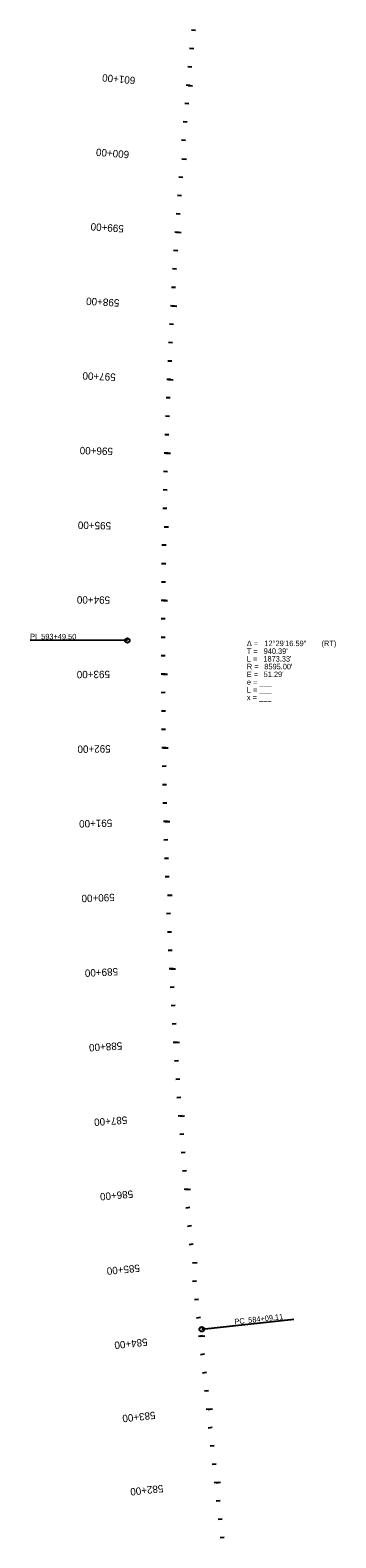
# Model space of a CAD drawing. Extents: x 16453950 to 16454580, y 7022804 to 7039381.
# Drawn here: x 16453950 to 16454365, y 7024883 to 7026929 of the extents above; entities that cross this region are included whole.
import ezdxf

# ---------------------------------------------------------------- set-up
doc = ezdxf.new("R2010")
doc.units = 0
for name, color, linetype in [('TextAlignment', 7, 'Continuous'), ('TextAlignmentLrg', 7, 'Continuous'), ('TextAlignmentSml', 7, 'Continuous')]:
    doc.layers.add(name, color=color, linetype=linetype)

msp = doc.modelspace()

# ---------------------------------------------------------------- linework, layer by layer
at = {"layer": 'TextAlignment'}
for p, q in [((16454082.3, 7026100.9), (16453950.3, 7026101.1)), ((16453950.3, 7026101.1), (16453950.3, 7026101.1)), ((16454183.3, 7025166), (16454308.5, 7025179.5)), ((16454308.5, 7025179.5), (16454308.5, 7025179.5))]:
    msp.add_line(p, q, dxfattribs=at)
for centre in [(16454082.3, 7026100.9), (16454183.3, 7025166)]:
    msp.add_circle(centre, 3.12, dxfattribs=at)
at = {"layer": 'TextAlignmentLrg'}
for p, q in [((16454167.8, 7026854.1), (16454162.3, 7026854.5)), ((16454156.4, 7026754.6), (16454162.5, 7026754.2)), ((16454152.3, 7026654.7), (16454146.8, 7026655)), ((16454146.3, 7026554.8), (16454140.8, 7026555.1)), ((16454141.4, 7026455), (16454136, 7026455.2)), ((16454137.8, 7026355), (16454132.3, 7026355.2)), ((16454132.2, 7026255.1), (16454138.3, 7026255)), ((16454133.9, 7026155.1), (16454128.4, 7026155.1)), ((16454133.7, 7026055.1), (16454128.2, 7026055.1)), ((16454134.6, 7025955.1), (16454129.2, 7025955)), ((16454136.8, 7025855.1), (16454131.3, 7025855)), ((16454137, 7025755), (16454143.1, 7025755.3)), ((16454144.5, 7025655.3), (16454139.1, 7025655)), ((16454150.2, 7025555.4), (16454144.7, 7025555.1)), ((16454156.9, 7025455.6), (16454151.5, 7025455.2)), ((16454164.9, 7025356), (16454159.4, 7025355.5)), ((16454170.9, 7025256.1), (16454177, 7025256.7)), ((16454184.2, 7025156.9), (16454178.8, 7025156.3)), ((16454195, 7025057.5), (16454189.5, 7025056.9)), ((16454205.7, 7024958.1), (16454200.3, 7024957.5))]:
    msp.add_line(p, q, dxfattribs=at)
at = {"layer": 'TextAlignmentSml'}
for p, q in [((16454174.8, 7026928.7), (16454169.4, 7026929.3)), ((16454172.4, 7026903.8), (16454166.9, 7026904.4)), ((16454170, 7026879), (16454164.6, 7026879.5)), ((16454164.7, 7026854.3), (16454170.8, 7026853.8)), ((16454165.6, 7026829.2), (16454160.2, 7026829.6)), ((16454163.5, 7026804.2), (16454158, 7026804.7)), ((16454161.4, 7026779.3), (16454156, 7026779.8)), ((16454156.4, 7026754.6), (16454162.5, 7026754.2)), ((16454157.6, 7026729.5), (16454152.1, 7026729.9)), ((16454155.7, 7026704.5), (16454150.3, 7026704.9)), ((16454154, 7026679.6), (16454148.5, 7026680)), ((16454149.2, 7026654.9), (16454155.3, 7026654.5)), ((16454150.7, 7026629.7), (16454145.2, 7026630.1)), ((16454149.1, 7026604.8), (16454143.7, 7026605.1)), ((16454147.7, 7026579.8), (16454142.2, 7026580.1)), ((16454143.2, 7026555), (16454149.3, 7026554.7)), ((16454145, 7026529.9), (16454139.5, 7026530.2)), ((16454143.7, 7026504.9), (16454138.3, 7026505.2)), ((16454142.5, 7026479.9), (16454137.1, 7026480.2)), ((16454138.4, 7026455.1), (16454144.5, 7026454.8)), ((16454140.4, 7026430), (16454134.9, 7026430.2)), ((16454139.4, 7026405), (16454134, 7026405.2)), ((16454138.6, 7026380), (16454133.1, 7026380.2)), ((16454134.7, 7026355.1), (16454140.8, 7026354.9)), ((16454137, 7026330), (16454131.6, 7026330.2)), ((16454136.3, 7026305.1), (16454130.9, 7026305.2)), ((16454135.8, 7026280.1), (16454130.3, 7026280.2)), ((16454132.2, 7026255.1), (16454138.3, 7026255)), ((16454134.8, 7026230.1), (16454129.3, 7026230.2)), ((16454134.4, 7026205.1), (16454128.9, 7026205.1)), ((16454134.1, 7026180.1), (16454128.6, 7026180.1)), ((16454130.8, 7026155.1), (16454136.9, 7026155.1)), ((16454133.7, 7026130.1), (16454128.3, 7026130.1)), ((16454133.6, 7026105.1), (16454128.2, 7026105.1)), ((16454133.6, 7026080.1), (16454128.2, 7026080.1)), ((16454130.6, 7026055.1), (16454136.7, 7026055.1)), ((16454133.8, 7026030.1), (16454128.4, 7026030)), ((16454134, 7026005.1), (16454128.6, 7026005)), ((16454134.3, 7025980.1), (16454128.8, 7025980)), ((16454131.6, 7025955), (16454137.7, 7025955.1)), ((16454135.1, 7025930.1), (16454129.6, 7025930)), ((16454135.6, 7025905.1), (16454130.1, 7025905)), ((16454136.1, 7025880.1), (16454130.7, 7025880)), ((16454133.7, 7025855), (16454139.8, 7025855.2)), ((16454137.5, 7025830.1), (16454132, 7025830)), ((16454138.3, 7025805.1), (16454132.8, 7025804.9)), ((16454139.1, 7025780.1), (16454133.7, 7025779.9)), ((16454137, 7025755), (16454143.1, 7025755.3)), ((16454141.1, 7025730.2), (16454135.6, 7025730)), ((16454142.2, 7025705.2), (16454136.7, 7025705)), ((16454143.3, 7025680.2), (16454137.9, 7025680)), ((16454141.5, 7025655.1), (16454147.6, 7025655.4)), ((16454145.8, 7025630.3), (16454140.4, 7025630)), ((16454147.2, 7025605.3), (16454141.7, 7025605)), ((16454148.6, 7025580.4), (16454143.2, 7025580)), ((16454147.1, 7025555.2), (16454153.2, 7025555.6)), ((16454151.7, 7025530.5), (16454146.3, 7025530.1)), ((16454153.4, 7025505.5), (16454148, 7025505.2)), ((16454155.1, 7025480.6), (16454149.7, 7025480.2)), ((16454153.9, 7025455.4), (16454160, 7025455.9)), ((16454158.8, 7025430.7), (16454153.4, 7025430.3)), ((16454160.8, 7025405.8), (16454155.3, 7025405.4)), ((16454162.8, 7025380.9), (16454157.3, 7025380.4)), ((16454161.8, 7025355.7), (16454167.9, 7025356.2)), ((16454167, 7025331.1), (16454161.6, 7025330.6)), ((16454169.3, 7025306.2), (16454163.8, 7025305.7)), ((16454171.6, 7025281.3), (16454166.2, 7025280.8)), ((16454170.9, 7025256.1), (16454177, 7025256.7)), ((16454176.4, 7025231.5), (16454171, 7025231)), ((16454179, 7025206.6), (16454173.5, 7025206.1)), ((16454181.6, 7025181.8), (16454176.1, 7025181.2)), ((16454181.2, 7025156.6), (16454187.3, 7025157.2)), ((16454186.9, 7025132.1), (16454181.5, 7025131.5)), ((16454189.6, 7025107.2), (16454184.2, 7025106.6)), ((16454192.3, 7025082.3), (16454186.9, 7025081.8)), ((16454191.9, 7025057.2), (16454198, 7025057.8)), ((16454197.6, 7025032.6), (16454192.2, 7025032)), ((16454200.3, 7025007.8), (16454194.9, 7025007.2)), ((16454203, 7024982.9), (16454197.6, 7024982.3)), ((16454202.7, 7024957.7), (16454208.7, 7024958.4)), ((16454208.4, 7024933.2), (16454203, 7024932.6)), ((16454211.1, 7024908.4), (16454205.6, 7024907.8)), ((16454213.7, 7024883.5), (16454208.3, 7024882.9))]:
    msp.add_line(p, q, dxfattribs=at)

# ---------------------------------------------------------------- texts
at = {"layer": 'TextAlignment'}
for s, rotation, p in [('PI ', 359.917, (16453950.3, 7026102.5)), ('593+49.50', 359.917, (16453965.3, 7026102.4)), ('PC', 6.161, (16454228.2, 7025172.5)), ('584+09.11', 6.161, (16454246.8, 7025174.5))]:
    msp.add_text(s, height=7.5, rotation=rotation, dxfattribs=at).set_placement(p)
for s, p in [('Δ = ', (16454244.6, 7026093.2)), ('12°29\'16.59"', (16454268.4, 7026093.2)), (' (RT)', (16454343.2, 7026093.2)), ('T = ', (16454244.6, 7026082.7)), ('L = ', (16454244.6, 7026072.2)), ("1873.33'", (16454267, 7026072.2)), ("940.39'", (16454267.4, 7026082.7)), ('R = ', (16454244.6, 7026061.7)), ('E = ', (16454244.6, 7026051.2)), ("51.29'", (16454267.4, 7026051.2)), ("8595.00'", (16454268.3, 7026061.7)), ('e = ___ ', (16454244.6, 7026040.7)), ('L = ___', (16454244.6, 7026030.2)), ('x = ___', (16454244.6, 7026019.7))]:
    msp.add_text(s, height=7.5, dxfattribs=at).set_placement(p)
at = {"layer": 'TextAlignmentLrg'}
for s, rotation, p in [('600+00', 175.5559, (16454085.1, 7026765.2)), ('595+00', 178.8889, (16454060.3, 7026261.5)), ('590+00', 182.222, (16454064.9, 7025757.3)), ('585+00', 185.5551, (16454098.8, 7025254.1))]:
    msp.add_text(s, height=10.02, rotation=rotation, dxfattribs=at).set_placement(p)
at = {"layer": 'TextAlignmentSml'}
for s, rotation, p in [('601+00', 174.8892, (16454093.5, 7026865.7)), ('600+00', 175.5559, (16454085.1, 7026765.2)), ('599+00', 176.2225, (16454077.8, 7026664.6)), ('598+00', 176.8891, (16454071.7, 7026563.9)), ('597+00', 177.5557, (16454066.7, 7026463.2)), ('596+00', 178.2223, (16454062.9, 7026362.4)), ('595+00', 178.8889, (16454060.3, 7026261.5)), ('594+00', 179.5556, (16454058.9, 7026160.7)), ('593+00', 180.2222, (16454058.7, 7026059.8)), ('592+00', 180.8888, (16454059.6, 7025958.9)), ('591+00', 181.5554, (16454061.7, 7025858.1)), ('590+00', 182.222, (16454064.9, 7025757.3)), ('589+00', 182.8887, (16454069.4, 7025656.5)), ('588+00', 183.5553, (16454075, 7025555.8)), ('587+00', 184.2219, (16454081.8, 7025455.1)), ('586+00', 184.8885, (16454089.7, 7025354.6)), ('585+00', 185.5551, (16454098.8, 7025254.1)), ('584+00', 186.161, (16454109.1, 7025153.8)), ('583+00', 186.161, (16454119.9, 7025054.4)), ('582+00', 186.161, (16454130.6, 7024955))]:
    msp.add_text(s, height=10.02, rotation=rotation, dxfattribs=at).set_placement(p)

doc.saveas('drawing.dxf')
